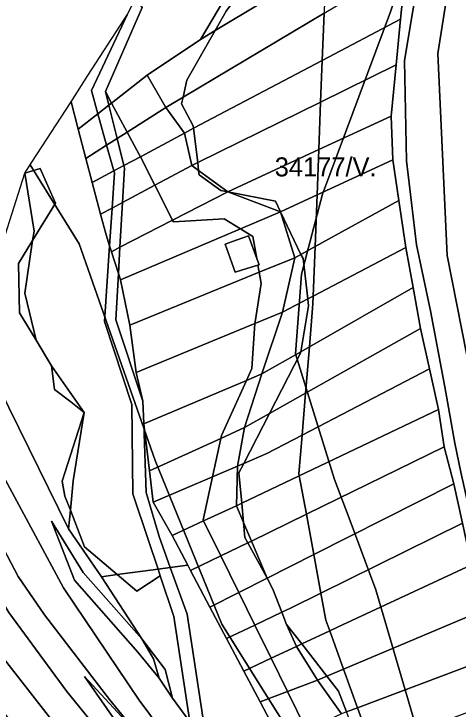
# Model space of a CAD drawing. Extents: x -537068 to -534056, y -1176840 to -1172401.
# Drawn here: x -536794 to -536677.3, y -1173485.4 to -1173302.6 of the extents above; entities that cross this region are included whole.
import ezdxf

# ---------------------------------------------------------------- set-up
doc = ezdxf.new("R2010")
doc.units = 0
for name, color, linetype in [('95560013', 7, 'Continuous'), ('95610013', 7, 'Continuous'), ('95640013', 7, 'Continuous'), ('95660013', 7, 'Continuous')]:
    doc.layers.add(name, color=color, linetype=linetype)

msp = doc.modelspace()

# ---------------------------------------------------------------- linework, layer by layer
at = {"layer": '95560013'}
for points in [[(-536654.5, -1173491.81), (-536663.25, -1173469.06), (-536671.19, -1173446.92), (-536676.53, -1173423.04), (-536678.08, -1173415.43), (-536680.7, -1173400.62), (-536684.49, -1173380.62), (-536688.17, -1173363.3), (-536690.79, -1173341.22), (-536691.31, -1173314.96), (-536689.31, -1173302.74), (-536687.2, -1173290.63), (-536684.49, -1173275.8), (-536677.84, -1173283.03), (-536682.55, -1173312.96), (-536680.16, -1173366.09), (-536673.71, -1173398.53), (-536669.22, -1173425.17), (-536656.16, -1173465.22), (-536646.8, -1173488.93)], [(-536656.55, -1173492.46), (-536661.23, -1173481.18), (-536665.57, -1173470.7), (-536669.79, -1173458.99), (-536673.76, -1173447.43), (-536676.13, -1173436.47), (-536678.36, -1173426.14), (-536680.95, -1173416.4), (-536682.37, -1173406.56), (-536684.76, -1173395.91), (-536687.14, -1173385.29), (-536689.09, -1173374.5), (-536691, -1173363.98), (-536692.81, -1173351.61), (-536694.37, -1173340.91), (-536694.88, -1173329.44), (-536693.55, -1173316.01), (-536692.35, -1173303.97), (-536690.92, -1173289.5)], [(-536687.2, -1173290.63), (-536689.31, -1173302.74), (-536691.31, -1173314.96), (-536690.79, -1173341.22), (-536688.17, -1173363.3), (-536684.49, -1173380.62), (-536680.7, -1173400.62), (-536678.08, -1173415.43), (-536676.53, -1173423.04), (-536671.19, -1173446.92), (-536663.25, -1173469.06), (-536654.5, -1173491.81)]]:
    msp.add_lwpolyline(points, dxfattribs=at)
for points in [[(-536641.24, -1173479.59), (-536633.17, -1173496.83), (-536617.57, -1173526.09), (-536612.17, -1173532.59), (-536616.71, -1173549.35), (-536635.75, -1173513.66), (-536646.8, -1173488.93), (-536656.16, -1173465.22), (-536669.22, -1173425.17), (-536673.71, -1173398.53), (-536680.16, -1173366.09), (-536682.55, -1173312.96), (-536677.84, -1173283.03), (-536670.88, -1173290.59), (-536673.51, -1173312.53), (-536673.26, -1173346.56), (-536669.56, -1173383.4), (-536663.56, -1173415.01), (-536652.88, -1173449.34)], [(-536712.48, -1173302.36), (-536690.92, -1173289.5), (-536692.35, -1173303.97), (-536712.95, -1173314.83)], [(-536693.55, -1173316.01), (-536713.37, -1173325.78), (-536712.95, -1173314.83), (-536692.35, -1173303.97)], [(-536694.88, -1173329.44), (-536713.85, -1173338.23), (-536713.37, -1173325.78), (-536693.55, -1173316.01)], [(-536714.31, -1173350.16), (-536713.85, -1173338.23), (-536694.88, -1173329.44), (-536694.37, -1173340.91)], [(-536714.31, -1173350.16), (-536694.37, -1173340.91), (-536692.81, -1173351.61), (-536714.83, -1173363.76)], [(-536715.32, -1173376.77), (-536714.83, -1173363.76), (-536692.81, -1173351.61), (-536691, -1173363.98)], [(-536691, -1173363.98), (-536689.09, -1173374.5), (-536716.34, -1173390.11), (-536715.4, -1173378.79), (-536715.32, -1173376.77)], [(-536716.34, -1173390.11), (-536689.09, -1173374.5), (-536687.14, -1173385.29), (-536717.35, -1173402.33)], [(-536684.76, -1173395.91), (-536718.26, -1173413.33), (-536717.35, -1173402.33), (-536687.14, -1173385.29)], [(-536719, -1173424.01), (-536719.1, -1173423.47), (-536718.26, -1173413.33), (-536684.76, -1173395.91), (-536682.37, -1173406.56)], [(-536717.13, -1173434.13), (-536719, -1173424.01), (-536682.37, -1173406.56), (-536680.95, -1173416.4)], [(-536715.17, -1173444.76), (-536717.13, -1173434.13), (-536680.95, -1173416.4), (-536678.36, -1173426.14)], [(-536676.13, -1173436.47), (-536713.3, -1173454.89), (-536715.17, -1173444.76), (-536678.36, -1173426.14)], [(-536710.97, -1173464.79), (-536712, -1173461.94), (-536713.3, -1173454.89), (-536676.13, -1173436.47), (-536673.76, -1173447.43), (-536708.93, -1173463.83)], [(-536673.76, -1173447.43), (-536669.79, -1173458.99), (-536707.33, -1173474.88), (-536710.97, -1173464.79), (-536708.93, -1173463.83)], [(-536707.33, -1173474.88), (-536669.79, -1173458.99), (-536665.57, -1173470.7), (-536703.66, -1173485.04)], [(-536661.23, -1173481.18), (-536699.85, -1173495.61), (-536703.66, -1173485.04), (-536665.57, -1173470.7)]]:
    msp.add_lwpolyline(points, close=True, dxfattribs=at)
at = {"layer": '95610013'}
for points in [[(-536697.92, -1173281.27), (-536703.35, -1173284.22), (-536741.09, -1173306.98), (-536738.16, -1173301.84), (-536732.94, -1173294.58), (-536733.21, -1173292.33), (-536687.27, -1173262.34), (-536688.39, -1173271.56)], [(-536697.92, -1173281.27), (-536712.23, -1173295.85), (-536712.48, -1173302.36), (-536749.51, -1173324.44), (-536748.51, -1173319.99), (-536741.09, -1173306.98), (-536703.35, -1173284.22)], [(-536749.91, -1173326.21), (-536749.51, -1173324.44), (-536712.48, -1173302.36), (-536712.95, -1173314.83), (-536746.75, -1173332.65), (-536746.83, -1173331.97)], [(-536712.95, -1173314.83), (-536713.37, -1173325.78), (-536745.68, -1173341.69), (-536746.75, -1173332.65)], [(-536768.29, -1173326.05), (-536769.02, -1173326.62), (-536769.92, -1173323)], [(-536764.22, -1173333.64), (-536766.85, -1173335.32), (-536769.02, -1173326.62), (-536768.29, -1173326.05)], [(-536745.68, -1173341.69), (-536713.37, -1173325.78), (-536713.85, -1173338.23), (-536737.8, -1173349.34), (-536745.43, -1173343.75)], [(-536760.75, -1173340.14), (-536765.07, -1173342.46), (-536766.85, -1173335.32), (-536764.22, -1173333.64), (-536761.05, -1173339.56)], [(-536723.91, -1173354.62), (-536725.27, -1173351.79), (-536737.8, -1173349.34), (-536713.85, -1173338.23), (-536714.31, -1173350.16)], [(-536756.93, -1173347.64), (-536765.41, -1173352.16), (-536764.89, -1173343.17), (-536765.07, -1173342.46), (-536760.75, -1173340.14)], [(-536783.08, -1173352.35), (-536789.05, -1173362.13), (-536788.69, -1173359.7), (-536791.11, -1173344.5), (-536787.06, -1173343.27)], [(-536805.86, -1173384.88), (-536799.66, -1173371.28), (-536791.11, -1173344.5), (-536788.69, -1173359.7), (-536789.05, -1173362.13), (-536792.74, -1173368.17), (-536792.51, -1173381.19), (-536788.17, -1173388.4), (-536784.13, -1173395.11), (-536783.34, -1173401.31), (-536779.01, -1173404.62), (-536775.54, -1173407.39), (-536781.32, -1173425.44), (-536780.57, -1173429.38), (-536779.13, -1173433.09), (-536779.6, -1173438)], [(-536739.61, -1173348.99), (-536745.3, -1173344.86), (-536745.43, -1173343.75), (-536737.8, -1173349.34)], [(-536756.93, -1173347.64), (-536752.27, -1173356.81), (-536766.1, -1173363.95), (-536765.41, -1173352.16)], [(-536723.91, -1173354.62), (-536714.31, -1173350.16), (-536714.83, -1173363.76), (-536718.54, -1173365.81)], [(-536752.27, -1173356.81), (-536752.03, -1173357.27), (-536738.68, -1173356.48), (-536734.44, -1173359.1), (-536765.97, -1173372.53), (-536766.5, -1173370.87), (-536766.1, -1173363.95)], [(-536730.16, -1173366.89), (-536732.33, -1173360.94), (-536736.54, -1173362.43), (-536738.46, -1173363.11), (-536735.8, -1173370.47), (-536733.87, -1173369.87), (-536729.84, -1173368.62), (-536729.5, -1173370.51), (-536763.54, -1173384.39), (-536765.97, -1173372.53), (-536734.44, -1173359.1), (-536731.21, -1173361.1)], [(-536714.83, -1173363.76), (-536715.32, -1173376.77), (-536716.77, -1173377.53), (-536718, -1173366.93), (-536718.54, -1173365.81)], [(-536729.5, -1173370.51), (-536728.96, -1173373.49), (-536730.6, -1173383.56), (-536730.63, -1173384), (-536761.87, -1173396.91), (-536763.54, -1173384.39)], [(-536767.21, -1173383.01), (-536766.5, -1173370.87), (-536765.97, -1173372.53), (-536763.54, -1173384.39), (-536761.87, -1173396.91), (-536760.07, -1173404.43)], [(-536716.77, -1173377.53), (-536715.32, -1173376.77), (-536715.4, -1173378.79), (-536716.34, -1173390.11), (-536718.57, -1173391.39), (-536716.56, -1173379.33)], [(-536761.05, -1173483.01), (-536780.9, -1173453.47), (-536811.63, -1173396.67), (-536807.24, -1173387.92), (-536805.86, -1173384.88), (-536779.6, -1173438), (-536770.95, -1173450.55), (-536760.36, -1173466.88), (-536775.8, -1173449.45), (-536784.13, -1173435.99), (-536778.05, -1173451.43), (-536761.41, -1173470.36), (-536755.8, -1173477.27), (-536752.34, -1173482.48), (-536747.73, -1173488.68), (-536747.24, -1173491.91), (-536746.21, -1173506.04), (-536750.93, -1173496.66)], [(-536760.07, -1173404.43), (-536761.87, -1173396.91), (-536730.63, -1173384), (-536731.44, -1173395.84), (-536732.86, -1173398.97), (-536759.86, -1173410.37)], [(-536718.57, -1173391.39), (-536716.34, -1173390.11), (-536717.35, -1173402.33), (-536726.8, -1173407.66), (-536718.64, -1173391.8)], [(-536810.37, -1173417.23), (-536816.78, -1173406.94), (-536811.63, -1173396.67), (-536780.9, -1173453.47), (-536761.05, -1173483.01), (-536750.93, -1173496.66), (-536746.21, -1173506.04), (-536744.94, -1173523.42), (-536761.35, -1173492.04), (-536768.87, -1173482.83), (-536785.92, -1173460.58), (-536792.86, -1173450.46)], [(-536732.86, -1173398.97), (-536739.45, -1173413.43), (-536739.62, -1173414.21), (-536758.35, -1173422.71), (-536759.86, -1173410.37)], [(-536733.54, -1173420.77), (-536726.8, -1173407.66), (-536717.35, -1173402.33), (-536718.26, -1173413.33), (-536727.48, -1173418.13)], [(-536792.86, -1173450.46), (-536785.92, -1173460.58), (-536768.87, -1173482.83), (-536761.35, -1173492.04), (-536775.44, -1173476.8), (-536763.71, -1173493.62), (-536744.91, -1173523.88), (-536743.87, -1173538.18), (-536746.73, -1173531.93), (-536753.8, -1173518.77), (-536765.21, -1173499.07), (-536780.04, -1173480.7), (-536795.33, -1173460.01), (-536821.63, -1173416.6), (-536816.78, -1173406.94), (-536810.37, -1173417.23)], [(-536759.21, -1173428.41), (-536759.86, -1173410.37), (-536758.35, -1173422.71), (-536757.35, -1173430.94), (-536752.4, -1173439.76), (-536748.29, -1173447.54), (-536752.87, -1173448.15), (-536755.82, -1173439.97)], [(-536739.62, -1173414.21), (-536741.81, -1173424.31), (-536757.35, -1173430.94), (-536758.35, -1173422.71)], [(-536719.1, -1173423.47), (-536719, -1173424.01), (-536734.11, -1173431.21), (-536734.84, -1173423.29), (-536733.54, -1173420.77), (-536727.48, -1173418.13), (-536718.26, -1173413.33)], [(-536771.14, -1173494.71), (-536755.71, -1173519.46), (-536747.53, -1173532.44), (-536753.8, -1173518.77), (-536746.73, -1173531.93), (-536743.87, -1173538.18), (-536743.18, -1173547.58), (-536743.51, -1173552.94), (-536749.9, -1173539.86), (-536761.32, -1173521.03), (-536772.15, -1173503.44), (-536803.76, -1173463.15), (-536826.22, -1173425.75), (-536821.63, -1173416.6), (-536795.33, -1173460.01), (-536780.04, -1173480.7), (-536765.21, -1173499.07), (-536753.8, -1173518.77)], [(-536752.4, -1173439.76), (-536757.35, -1173430.94), (-536741.81, -1173424.31), (-536744.26, -1173435.62), (-536744.12, -1173435.9)], [(-536734.11, -1173431.21), (-536719, -1173424.01), (-536717.13, -1173434.13), (-536731.55, -1173441.2), (-536733.64, -1173436.29)], [(-536803.76, -1173463.15), (-536772.15, -1173503.44), (-536761.32, -1173521.03), (-536774.9, -1173502.85), (-536763.32, -1173522.18), (-536749.07, -1173545.72), (-536761.32, -1173521.03), (-536749.9, -1173539.86), (-536743.51, -1173552.94), (-536744.08, -1173562.31), (-536747.31, -1173573.02), (-536750.25, -1173556.87), (-536767.15, -1173530.97), (-536777.98, -1173509.6), (-536808.59, -1173471.31), (-536818.95, -1173454.8), (-536832.27, -1173436.41), (-536830.84, -1173434.15), (-536828.87, -1173431.02), (-536826.22, -1173425.75)], [(-536770.95, -1173450.55), (-536779.6, -1173438), (-536779.13, -1173433.09), (-536775.39, -1173442.74), (-536766.84, -1173450)], [(-536715.17, -1173444.76), (-536727.46, -1173450.98), (-536731.55, -1173441.2), (-536717.13, -1173434.13)], [(-536739.6, -1173445.09), (-536747.56, -1173448.93), (-536748.29, -1173447.54), (-536752.4, -1173439.76), (-536744.12, -1173435.9)], [(-536731.55, -1173441.2), (-536732.49, -1173441.66), (-536733.27, -1173440.22), (-536733.64, -1173436.29)], [(-536727.46, -1173450.98), (-536732.49, -1173441.66), (-536731.55, -1173441.2)], [(-536734.86, -1173454.73), (-536742.46, -1173458.57), (-536747.56, -1173448.93), (-536739.6, -1173445.09)], [(-536723.54, -1173459.91), (-536725.91, -1173453.86), (-536727.46, -1173450.98), (-536715.17, -1173444.76), (-536713.3, -1173454.89), (-536721.3, -1173458.86)], [(-536747.56, -1173448.93), (-536742.46, -1173458.57), (-536738.12, -1173466.77), (-536733.58, -1173475.36), (-536729.28, -1173483.49), (-536723.75, -1173493.94), (-536720.72, -1173504.2), (-536718.46, -1173515.75), (-536717.9, -1173518.59), (-536718.65, -1173532.09), (-536719.77, -1173542.71), (-536735.42, -1173506.82), (-536740.51, -1173498.39), (-536743.58, -1173494.26), (-536743.73, -1173491.55), (-536748.44, -1173460.44), (-536752.87, -1173448.15), (-536748.29, -1173447.54)], [(-536752.34, -1173482.48), (-536754.26, -1173474.99), (-536760.36, -1173466.88), (-536770.95, -1173450.55), (-536766.84, -1173450), (-536761.69, -1173454.38), (-536755.51, -1173450.29), (-536751.91, -1173461.06), (-536747.73, -1173488.68)], [(-536742.46, -1173458.57), (-536734.86, -1173454.73), (-536730.67, -1173463.26), (-536738.12, -1173466.77)], [(-536722.3, -1173463.08), (-536723.54, -1173459.91), (-536721.3, -1173458.86), (-536713.3, -1173454.89), (-536712, -1173461.94), (-536710.97, -1173464.79), (-536718.31, -1173468.22)], [(-536738.12, -1173466.77), (-536730.67, -1173463.26), (-536726.38, -1173471.99), (-536733.58, -1173475.36)], [(-536711.71, -1173476.73), (-536718.31, -1173468.22), (-536710.97, -1173464.79), (-536707.33, -1173474.88)], [(-536722.07, -1173480.76), (-536729.28, -1173483.49), (-536733.58, -1173475.36), (-536726.38, -1173471.99)], [(-536706.54, -1173486.12), (-536708.69, -1173480.62), (-536711.71, -1173476.73), (-536707.33, -1173474.88), (-536703.66, -1173485.04)], [(-536717.1, -1173490.87), (-536723.75, -1173493.94), (-536729.28, -1173483.49), (-536722.07, -1173480.76)], [(-536699.85, -1173495.61), (-536702.44, -1173496.58), (-536706.54, -1173486.12), (-536703.66, -1173485.04)]]:
    msp.add_lwpolyline(points, close=True, dxfattribs=at)
at = {"layer": '95640013'}
for points in [[(-536733.87, -1173286.75), (-536733.94, -1173290.89), (-536736.03, -1173294.17), (-536744.95, -1173309.31), (-536758.92, -1173318.73), (-536768.29, -1173326.05), (-536769.92, -1173323), (-536760.29, -1173300.9), (-536761.91, -1173298.23), (-536747.77, -1173278.77), (-536739.98, -1173283.41)], [(-536732.94, -1173294.58), (-536738.16, -1173301.84), (-536741.09, -1173306.98), (-536744.95, -1173309.31), (-536736.03, -1173294.17), (-536733.21, -1173292.33)], [(-536769.02, -1173326.62), (-536771.89, -1173328.86), (-536773.59, -1173322.71), (-536764.23, -1173302.81), (-536761.91, -1173298.23), (-536760.29, -1173300.9), (-536769.92, -1173323)], [(-536765.04, -1173304.06), (-536764.23, -1173302.81), (-536773.59, -1173322.71), (-536771.89, -1173328.86), (-536777.06, -1173332.9), (-536778.96, -1173325.66), (-536774.53, -1173318.78)], [(-536744.95, -1173309.31), (-536741.09, -1173306.98), (-536748.51, -1173319.99), (-536749.51, -1173324.44), (-536754.07, -1173327.16), (-536758.92, -1173318.73)], [(-536764.22, -1173333.64), (-536768.29, -1173326.05), (-536758.92, -1173318.73), (-536754.07, -1173327.16)], [(-536749.91, -1173326.21), (-536746.83, -1173331.97), (-536746.75, -1173332.65), (-536749.16, -1173333.92), (-536754.07, -1173327.16), (-536749.51, -1173324.44)], [(-536769.77, -1173360.67), (-536768.85, -1173363.54), (-536770.17, -1173383.46), (-536762.97, -1173405.24), (-536762.75, -1173428.76), (-536758.67, -1173440.8), (-536756.08, -1173448.57), (-536766.84, -1173450), (-536775.39, -1173442.74), (-536779.13, -1173433.09), (-536778.39, -1173425.31), (-536775.54, -1173407.39), (-536784.13, -1173395.11), (-536788.17, -1173388.4), (-536791.11, -1173376.01), (-536789.05, -1173362.13), (-536783.08, -1173352.35), (-536787.06, -1173343.27), (-536791.11, -1173344.5), (-536789.23, -1173341.58), (-536778.96, -1173325.66), (-536777.06, -1173332.9), (-536775.05, -1173340.57), (-536773.38, -1173346.91), (-536771.19, -1173355.24)], [(-536766.85, -1173335.32), (-536769.61, -1173337.09), (-536771.89, -1173328.86), (-536769.02, -1173326.62)], [(-536754.07, -1173327.16), (-536749.16, -1173333.92), (-536760.75, -1173340.14), (-536761.05, -1173339.56), (-536764.22, -1173333.64)], [(-536775.05, -1173340.57), (-536777.06, -1173332.9), (-536771.89, -1173328.86), (-536769.61, -1173337.09)], [(-536756.93, -1173347.64), (-536760.75, -1173340.14), (-536749.16, -1173333.92), (-536747.21, -1173342.45)], [(-536749.16, -1173333.92), (-536746.75, -1173332.65), (-536745.68, -1173341.69), (-536747.21, -1173342.45)], [(-536766.85, -1173335.32), (-536765.07, -1173342.46), (-536767.72, -1173343.88), (-536769.61, -1173337.09)], [(-536773.38, -1173346.91), (-536775.05, -1173340.57), (-536769.61, -1173337.09), (-536767.72, -1173343.88)], [(-536767.72, -1173343.88), (-536765.07, -1173342.46), (-536764.89, -1173343.17), (-536765.41, -1173352.16), (-536768.19, -1173353.64), (-536767.58, -1173344.39)], [(-536756.93, -1173347.64), (-536747.21, -1173342.45), (-536745.43, -1173343.75), (-536745.3, -1173344.86), (-536739.61, -1173348.99), (-536737.8, -1173349.34), (-536752.27, -1173356.81)], [(-536747.21, -1173342.45), (-536745.68, -1173341.69), (-536745.43, -1173343.75)], [(-536773.38, -1173346.91), (-536767.72, -1173343.88), (-536767.58, -1173344.39), (-536768.19, -1173353.64), (-536771.19, -1173355.24)], [(-536752.27, -1173356.81), (-536737.8, -1173349.34), (-536723.91, -1173354.62), (-536734.44, -1173359.1), (-536738.68, -1173356.48), (-536752.03, -1173357.27)], [(-536737.8, -1173349.34), (-536725.27, -1173351.79), (-536723.91, -1173354.62)], [(-536768.35, -1173365.11), (-536768.85, -1173363.54), (-536768.19, -1173353.64), (-536765.41, -1173352.16), (-536766.1, -1173363.95)], [(-536769.77, -1173360.67), (-536771.19, -1173355.24), (-536768.19, -1173353.64), (-536768.85, -1173363.54)], [(-536729.5, -1173370.51), (-536729.84, -1173368.62), (-536729.56, -1173368.53), (-536730.16, -1173366.89), (-536731.21, -1173361.1), (-536734.44, -1173359.1), (-536723.91, -1173354.62), (-536720.19, -1173366.72)], [(-536720.19, -1173366.72), (-536723.91, -1173354.62), (-536718.54, -1173365.81)], [(-536729.56, -1173368.53), (-536729.84, -1173368.62), (-536733.87, -1173369.87), (-536735.8, -1173370.47), (-536738.46, -1173363.11), (-536736.54, -1173362.43), (-536732.33, -1173360.94), (-536730.16, -1173366.89)], [(-536788.17, -1173388.4), (-536792.51, -1173381.19), (-536792.74, -1173368.17), (-536789.05, -1173362.13), (-536791.11, -1173376.01)], [(-536762.97, -1173405.24), (-536770.17, -1173383.46), (-536768.85, -1173363.54), (-536768.35, -1173365.11), (-536766.5, -1173370.87), (-536767.21, -1173383.01), (-536760.07, -1173404.43), (-536759.86, -1173410.37), (-536759.21, -1173428.41), (-536755.82, -1173439.97), (-536752.87, -1173448.15), (-536756.08, -1173448.57), (-536758.67, -1173440.8), (-536762.75, -1173428.76)], [(-536768.35, -1173365.11), (-536766.1, -1173363.95), (-536766.5, -1173370.87)], [(-536723.37, -1173381), (-536730.63, -1173384), (-536730.6, -1173383.56), (-536728.96, -1173373.49), (-536729.5, -1173370.51), (-536720.19, -1173366.72)], [(-536718.54, -1173365.81), (-536718, -1173366.93), (-536716.77, -1173377.53), (-536723.37, -1173381), (-536720.19, -1173366.72)], [(-536723.37, -1173381), (-536716.77, -1173377.53), (-536716.56, -1173379.33), (-536718.57, -1173391.39), (-536728.82, -1173397.26)], [(-536728.82, -1173397.26), (-536732.86, -1173398.97), (-536731.44, -1173395.84), (-536730.63, -1173384), (-536723.37, -1173381)], [(-536718.57, -1173391.39), (-536718.64, -1173391.8), (-536726.8, -1173407.66), (-536733.37, -1173411.37), (-536728.82, -1173397.26)], [(-536779.01, -1173404.62), (-536783.34, -1173401.31), (-536784.13, -1173395.11), (-536775.54, -1173407.39)], [(-536728.82, -1173397.26), (-536733.37, -1173411.37), (-536739.62, -1173414.21), (-536739.45, -1173413.43), (-536732.86, -1173398.97)], [(-536781.32, -1173425.44), (-536775.54, -1173407.39), (-536778.39, -1173425.31), (-536779.13, -1173433.09), (-536780.57, -1173429.38)], [(-536733.54, -1173420.77), (-536735.2, -1173421.49), (-536733.37, -1173411.37), (-536726.8, -1173407.66)], [(-536739.62, -1173414.21), (-536733.37, -1173411.37), (-536735.2, -1173421.49), (-536741.81, -1173424.31)], [(-536735.51, -1173431.88), (-536744.12, -1173435.9), (-536744.26, -1173435.62), (-536741.81, -1173424.31), (-536735.2, -1173421.49)], [(-536733.54, -1173420.77), (-536734.84, -1173423.29), (-536734.11, -1173431.21), (-536735.51, -1173431.88), (-536735.2, -1173421.49)], [(-536733.64, -1173436.29), (-536733.27, -1173440.22), (-536732.49, -1173441.66), (-536739.6, -1173445.09), (-536744.12, -1173435.9), (-536735.51, -1173431.88)], [(-536734.11, -1173431.21), (-536733.64, -1173436.29), (-536735.51, -1173431.88)], [(-536784.13, -1173435.99), (-536775.8, -1173449.45), (-536760.36, -1173466.88), (-536757.27, -1173472.17), (-536755.8, -1173477.27), (-536761.41, -1173470.36), (-536778.05, -1173451.43)], [(-536739.6, -1173445.09), (-536732.49, -1173441.66), (-536727.46, -1173450.98), (-536734.86, -1173454.73)], [(-536761.69, -1173454.38), (-536766.84, -1173450), (-536756.08, -1173448.57), (-536755.51, -1173450.29)], [(-536743.73, -1173491.55), (-536743.58, -1173494.26), (-536747.73, -1173488.68), (-536751.91, -1173461.06), (-536755.51, -1173450.29), (-536756.08, -1173448.57), (-536752.87, -1173448.15), (-536748.44, -1173460.44)], [(-536730.67, -1173463.26), (-536734.86, -1173454.73), (-536727.46, -1173450.98), (-536725.91, -1173453.86), (-536723.54, -1173459.91)], [(-536730.67, -1173463.26), (-536723.54, -1173459.91), (-536722.3, -1173463.08), (-536719.71, -1173468.87), (-536726.38, -1173471.99)], [(-536722.3, -1173463.08), (-536718.31, -1173468.22), (-536719.71, -1173468.87)], [(-536757.27, -1173472.17), (-536760.36, -1173466.88), (-536754.26, -1173474.99), (-536752.34, -1173482.48), (-536755.8, -1173477.27)], [(-536714.17, -1173477.77), (-536722.07, -1173480.76), (-536726.38, -1173471.99), (-536719.71, -1173468.87)], [(-536714.17, -1173477.77), (-536719.71, -1173468.87), (-536718.31, -1173468.22), (-536711.71, -1173476.73)], [(-536775.44, -1173476.8), (-536761.35, -1173492.04), (-536744.94, -1173523.42), (-536744.91, -1173523.88), (-536763.71, -1173493.62)], [(-536708.69, -1173480.62), (-536706.54, -1173486.12), (-536707.89, -1173486.63), (-536714.17, -1173477.77), (-536711.71, -1173476.73)], [(-536722.07, -1173480.76), (-536714.17, -1173477.77), (-536707.89, -1173486.63), (-536717.1, -1173490.87)]]:
    msp.add_lwpolyline(points, close=True, dxfattribs=at)
at = {"layer": '95660013'}
for points in [[(-536685.37, -1173500), (-536698.87, -1173454), (-536705.63, -1173435.87), (-536709.69, -1173425), (-536720, -1173392), (-536718.37, -1173371), (-536712.87, -1173350), (-536695, -1173302), (-536683.87, -1173269), (-536670.37, -1173212), (-536661.31, -1173173)], [(-536661.31, -1173173), (-536670.37, -1173212), (-536683.87, -1173269), (-536695, -1173302), (-536712.87, -1173350), (-536718.37, -1173371), (-536720, -1173392), (-536709.69, -1173425), (-536705.63, -1173435.87), (-536698.87, -1173454), (-536685.37, -1173500)], [(-536721.19, -1173492), (-536728.01, -1173481.12), (-536739.37, -1173463), (-536756.87, -1173420), (-536776.81, -1173363), (-536789.66, -1173342.25), (-536789.23, -1173341.58), (-536778.96, -1173325.66), (-536774.53, -1173318.78), (-536765.04, -1173304.06), (-536764.23, -1173302.81), (-536761.91, -1173298.23), (-536754.11, -1173278.82), (-536726.26, -1173205.78), (-536678.67, -1173183.17)], [(-536863.34, -1173485.69), (-536859.16, -1173479.05), (-536853.98, -1173470.84), (-536847.94, -1173461.26), (-536842.65, -1173452.86), (-536838.18, -1173445.78), (-536832.27, -1173436.41), (-536830.84, -1173434.15), (-536828.87, -1173431.02), (-536826.22, -1173425.75), (-536821.63, -1173416.6), (-536816.78, -1173406.94), (-536811.63, -1173396.67), (-536807.24, -1173387.92), (-536805.86, -1173384.88), (-536799.66, -1173371.28), (-536791.11, -1173344.5), (-536789.66, -1173342.25), (-536776.81, -1173363), (-536756.87, -1173420), (-536739.37, -1173463), (-536728.01, -1173481.12), (-536721.19, -1173492)]]:
    msp.add_lwpolyline(points, dxfattribs=at)

# ---------------------------------------------------------------- texts
msp.add_text('34177/V.', height=5, rotation=0, dxfattribs=at).set_placement((-536725.44, -1173345.31))

doc.saveas('drawing.dxf')
